// Mitsubishi GX Works2 project: 三菱模版   PLC: FX3U/FX3UC

PROGRAM MAIN
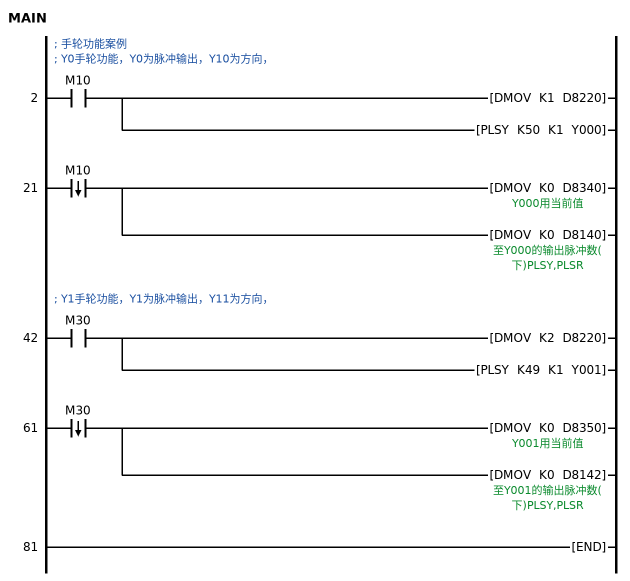
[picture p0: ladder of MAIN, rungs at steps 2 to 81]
; 手轮功能案例
; Y0手轮功能，Y0为脉冲输出，Y10为方向，
2     LD      M10
      DMOV    K1 D8220
        [note] 设置D8220为1，触发 Y0 手轮
      PLSY    K50 K1 Y000
        [note] 输入一个高速计数，输出50个脉冲
21    LDF     M10
      DMOV    K0 D8340  ; Y000用当前值
      DMOV    K0 D8140  ; 至Y000的输出脉冲数(下)PLSY,PLSR
; Y1手轮功能，Y1为脉冲输出，Y11为方向，
42    LD      M30
      DMOV    K2 D8220
        [note] 设置D8220为2，触发 Y1手轮
      PLSY    K49 K1 Y001
        [note] 输入一个高速计数，输出49个脉冲
61    LDF     M30
      DMOV    K0 D8350  ; Y001用当前值
      DMOV    K0 D8142  ; 至Y001的输出脉冲数(下)PLSY,PLSR
81    END
END_PROGRAM

// device comments not shown above
C10  ; CCD1拍照连续不良计数
C11  ; CCD2连续不良计数
